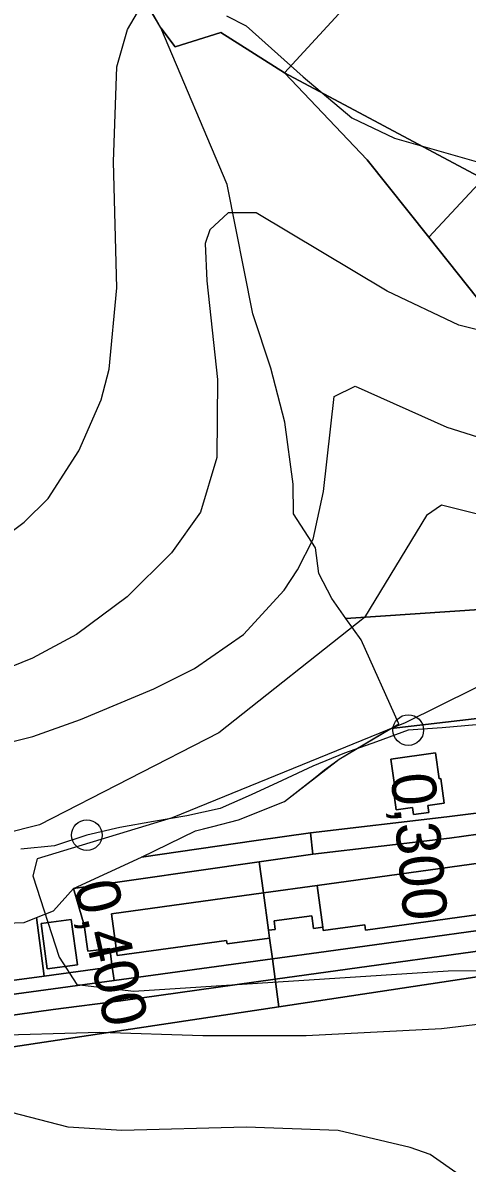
# Model space of a CAD drawing. Extents: x -510989 to -501240, y -1184665 to -1176089.
# Drawn here: x -504976.6 to -504845.9, y -1180942.6 to -1180607.1 of the extents above; entities that cross this region are included whole.
import ezdxf

# ---------------------------------------------------------------- set-up
doc = ezdxf.new("R2010")
doc.units = 0
for name, color, linetype in [('lesni_pozemek', 7, 'Continuous'), ('ostatni_plocha_x_draha', 7, 'Continuous'), ('ostatni_plocha_x_manipulacni_plocha', 7, 'Continuous'), ('popis', 7, 'Continuous'), ('STAV_zaplavove_uzemi', 7, 'Continuous'), ('trasovani_toku', 7, 'Continuous'), ('trvaly_travni_porost', 7, 'Continuous'), ('vrstevnice_01', 7, 'Continuous'), ('vrstevnice_02', 7, 'Continuous'), ('zastavena_plocha_a_nadvori', 7, 'Continuous')]:
    doc.layers.add(name, color=color, linetype=linetype)

msp = doc.modelspace()

# ---------------------------------------------------------------- linework, layer by layer
at = {"layer": 'lesni_pozemek'}
for points in [[(-504778.12, -1180775.36), (-504881.56, -1180782.32), (-504885.75, -1180776.42), (-504889.55, -1180769.13), (-504890.55, -1180761.5), (-504896.97, -1180751.57), (-504897.07, -1180742.79), (-504899.58, -1180724.53), (-504903.69, -1180708.68), (-504909, -1180692.68), (-504916.51, -1180654.59), (-504935.99, -1180608.54), (-504931.77, -1180614.16), (-504918.37, -1180609.9), (-504899.64, -1180621.82), (-504875.35, -1180647.35), (-504857.2, -1180670.16), (-504840.1, -1180691.66)], [(-505061.03, -1180977.99), (-505070, -1180922), (-504901.28, -1180896.57), (-504813.81, -1180883.39), (-504775.02, -1180922.63), (-504752.9, -1180947.58)]]:
    msp.add_lwpolyline(points, dxfattribs=at)
msp.add_lwpolyline([(-504778.12, -1180775.36), (-504774.09, -1180803.74), (-504868.25, -1180814.65), (-504865.99, -1180813.32), (-504877.12, -1180788.56), (-504881.56, -1180782.32)], close=True, dxfattribs=at)
at = {"layer": 'ostatni_plocha_x_draha'}
for points in [[(-504813.52, -1180870.15), (-504809.78, -1180869.64), (-504808.97, -1180875.47), (-504820.1, -1180877.02), (-504902.38, -1180888.46), (-504903.2, -1180882.42), (-504887.4, -1180880.26)], [(-504903.2, -1180882.42), (-504902.38, -1180888.46), (-504947.79, -1180894.78), (-504967.64, -1180897.41), (-505034.97, -1180906.78), (-505082.62, -1180915.45), (-505097.23, -1180920.86), (-505099.02, -1180907.99), (-505090.37, -1180907.46), (-505082.68, -1180906.98), (-504949.75, -1180888.79)]]:
    msp.add_lwpolyline(points, close=True, dxfattribs=at)
at = {"layer": 'ostatni_plocha_x_manipulacni_plocha'}
for points in [[(-504794.68, -1180513.8), (-504787.11, -1180516.78), (-504752.69, -1180548.72), (-504748.1, -1180552.99), (-504841.23, -1180653), (-504899.64, -1180621.82), (-504883.7, -1180604.44), (-504828.67, -1180545.06), (-504805.78, -1180520.45), (-504801.13, -1180516)], [(-504729.03, -1180772.34), (-504722.98, -1180823.87), (-504772.69, -1180830.81), (-504851.89, -1180840.66), (-504891.96, -1180845.4), (-504907.99, -1180847.69), (-504941.74, -1180852.51), (-504925.8, -1180844.85), (-504920.73, -1180843.54), (-504913.22, -1180841.6), (-504899.67, -1180836.13), (-504890.59, -1180829.07), (-504887.89, -1180826.89), (-504883.58, -1180823.67), (-504871.07, -1180816.31), (-504868.25, -1180814.65), (-504774.09, -1180803.74), (-504778.12, -1180775.36)], [(-504868.37, -1180823.7), (-504867.33, -1180831.28), (-504867.82, -1180831.35), (-504866.82, -1180838.63), (-504861.96, -1180837.96), (-504861.69, -1180839.99), (-504857.23, -1180839.38), (-504857.51, -1180837.35), (-504852.65, -1180836.69), (-504853.65, -1180829.4), (-504854.15, -1180829.46), (-504855.19, -1180821.88)], [(-504907.99, -1180847.69), (-504891.96, -1180845.4), (-504891.28, -1180851.67), (-504907.12, -1180853.94), (-504961.67, -1180861.76), (-504941.74, -1180852.51)], [(-504907.12, -1180853.94), (-504905.86, -1180863.03), (-504950.53, -1180869.21), (-504948.83, -1180881.52), (-504916.66, -1180877.04), (-504916.52, -1180878.08), (-504904.04, -1180876.34), (-504903.2, -1180882.42), (-504949.75, -1180888.79), (-504950.31, -1180884.77), (-504951.06, -1180879.42), (-504957.51, -1180880.25), (-504958.55, -1180872.52), (-504961.67, -1180861.76)], [(-504967.56, -1180868.31), (-504961.67, -1180861.76), (-504958.55, -1180872.52), (-504957.51, -1180880.25), (-504951.06, -1180879.42), (-504950.31, -1180884.77), (-504970.29, -1180887.57), (-504972.62, -1180870.33)], [(-504976.25, -1180871.79), (-504972.62, -1180870.33), (-504970.29, -1180887.57), (-505005.53, -1180892.29), (-505008.04, -1180869.77), (-504995.29, -1180872.45)], [(-504962.35, -1180870.89), (-504971.22, -1180872.11), (-504969.42, -1180885.39), (-504960.55, -1180884.19)], [(-504820.1, -1180877.02), (-504808.97, -1180875.47), (-504808, -1180882.51), (-504813.81, -1180883.39), (-504901.28, -1180896.57), (-504902.38, -1180888.46)]]:
    msp.add_lwpolyline(points, close=True, dxfattribs=at)
for points in [[(-504883.7, -1180604.44), (-504899.64, -1180621.82), (-504918.37, -1180609.9), (-504931.77, -1180614.16), (-504935.99, -1180608.54), (-504945.65, -1180591.49)], [(-504586.22, -1180827.45), (-504620.9, -1180827.94), (-504638.76, -1180828.03), (-504676.14, -1180828.22), (-504700.58, -1180828.72), (-504724.11, -1180830.13), (-504767.04, -1180835.38), (-504813.61, -1180841.75), (-504817.37, -1180842.26), (-504851.11, -1180846.92), (-504891.28, -1180851.67), (-504891.96, -1180845.4), (-504851.89, -1180840.66), (-504772.69, -1180830.81), (-504722.98, -1180823.87), (-504702, -1180822.23), (-504678.51, -1180822.08), (-504634.51, -1180821.81), (-504620.72, -1180821.72), (-504586.77, -1180821.19)], [(-504824.09, -1180851.79), (-504890.06, -1180860.84), (-504905.86, -1180863.03), (-504907.12, -1180853.94), (-504891.28, -1180851.67), (-504851.11, -1180846.92), (-504817.37, -1180842.26)], [(-504813.52, -1180870.15), (-504887.4, -1180880.26), (-504903.2, -1180882.42), (-504904.04, -1180876.34), (-504904.35, -1180874.06), (-504902.37, -1180873.79), (-504902.71, -1180871.31), (-504891.61, -1180869.79), (-504891.09, -1180873.55), (-504888.37, -1180873.18), (-504888.23, -1180874.17), (-504876, -1180872.49), (-504875.79, -1180873.98), (-504827.55, -1180867.35)], [(-505005.53, -1180892.29), (-504970.29, -1180887.57), (-504950.31, -1180884.77), (-504949.75, -1180888.79), (-505082.68, -1180906.98)], [(-505034.97, -1180906.78), (-504967.64, -1180897.41), (-504947.79, -1180894.78), (-504902.38, -1180888.46), (-504901.28, -1180896.57), (-505070, -1180922)]]:
    msp.add_lwpolyline(points, dxfattribs=at)
at = {"layer": 'popis'}
msp.add_lwpolyline([(-504995.29, -1180872.45), (-504976.25, -1180871.79), (-504972.62, -1180870.33), (-504967.56, -1180868.31), (-504961.67, -1180861.76), (-504941.74, -1180852.51), (-504925.8, -1180844.85), (-504913.22, -1180841.6), (-504899.67, -1180836.13), (-504883.58, -1180823.67), (-504865.99, -1180813.32), (-504877.12, -1180788.56), (-504881.56, -1180782.32), (-504885.75, -1180776.42), (-504889.55, -1180769.13), (-504890.55, -1180761.5), (-504896.97, -1180751.57), (-504897.07, -1180742.79), (-504899.58, -1180724.53), (-504903.69, -1180708.68), (-504909, -1180692.68), (-504916.51, -1180654.59), (-504935.99, -1180608.54), (-504968.37, -1180553.81)], dxfattribs=at)
at = {"layer": 'STAV_zaplavove_uzemi'}
msp.add_spline([(-504826.46, -1182247.73), (-504827.62, -1182204.68), (-504817.15, -1182165.12), (-504791.55, -1182113.93), (-504727.56, -1182034.81), (-504708.94, -1182017.35), (-504669.38, -1181991.76), (-504649.6, -1181961.5), (-504628.66, -1181917.29), (-504601.9, -1181867.26), (-504597.24, -1181809.08), (-504585.16, -1181766.79), (-504596.8, -1181741.4), (-504604.2, -1181726.59), (-504633.82, -1181658.9), (-504646.51, -1181600.72), (-504660.26, -1181556.29), (-504751.04, -1181459.08), (-504798.4, -1181384.84), (-504826.55, -1181347.73), (-504862.39, -1181315.73), (-504866.23, -1181265.81), (-504862.39, -1181205.66), (-504853.43, -1181164.7), (-504793.92, -1181116.47), (-504755.84, -1181064.64), (-504725.17, -1181018.1), (-504649.01, -1180947.23), (-504594, -1180900.69), (-504545.35, -1180879.53), (-504377.38, -1180832.83), (-504317.01, -1180808.36), (-504368.93, -1180802.59), (-504426.63, -1180826.63), (-504542.02, -1180859.32)], degree=3, dxfattribs=at)
at = {"layer": 'trasovani_toku'}
for p, q in [((-504863.23, -1180815.15), (-504872.6, -1180818.66)), ((-504853.26, -1180814.46), (-504863.23, -1180815.15)), ((-504843.29, -1180813.6), (-504853.26, -1180814.46)), ((-504872.6, -1180818.66), (-504882.04, -1180821.94)), ((-504882.04, -1180821.94), (-504891.27, -1180825.8)), ((-504891.27, -1180825.8), (-504900.35, -1180829.99)), ((-504900.35, -1180829.99), (-504909.42, -1180834.19)), ((-504909.42, -1180834.19), (-504918.56, -1180838.26)), ((-504918.56, -1180838.26), (-504928.34, -1180840.35)), ((-504938.19, -1180842.06), (-504948.03, -1180843.83)), ((-504928.34, -1180840.35), (-504938.19, -1180842.06)), ((-504957.78, -1180846.07), (-504967.28, -1180849.19)), ((-504948.03, -1180843.83), (-504957.78, -1180846.07)), ((-504967.28, -1180849.19), (-504977.23, -1180850.18))]:
    msp.add_line(p, q, dxfattribs=at)
for centre in [(-504863.23, -1180815.15), (-504957.78, -1180846.07)]:
    msp.add_circle(centre, 4.5, dxfattribs=at)
at = {"layer": 'trvaly_travni_porost'}
for points in [[(-504875.35, -1180647.35), (-504899.64, -1180621.82), (-504841.23, -1180653), (-504857.2, -1180670.16)], [(-504841.23, -1180653), (-504745.8, -1180703.95), (-504702.57, -1180727.02), (-504697, -1180730), (-504696.34, -1180738.75), (-504714.5, -1180740.39), (-504732.28, -1180732.9), (-504736.03, -1180735.08), (-504781.24, -1180713.72), (-504801.06, -1180715.91), (-504840.1, -1180691.66), (-504857.2, -1180670.16)]]:
    msp.add_lwpolyline(points, close=True, dxfattribs=at)
at = {"layer": 'vrstevnice_01'}
for points in [[(-504828.31, -1180701), (-504848.41, -1180696), (-504869.41, -1180686), (-504908, -1180663), (-504916.19, -1180663), (-504921.59, -1180668), (-504923, -1180672), (-504922.5, -1180683), (-504919.31, -1180712), (-504919.59, -1180735), (-504924.31, -1180751), (-504932.91, -1180763), (-504945.91, -1180776), (-504960.81, -1180787), (-504973.81, -1180794), (-504988.59, -1180800)], [(-504611.91, -1180776), (-504652.81, -1180783), (-504695.91, -1180784), (-504731.19, -1180783), (-504746.31, -1180779), (-504783.09, -1180763), (-504798.81, -1180759), (-504829.41, -1180755), (-504853.5, -1180749), (-504857.91, -1180752), (-504876.09, -1180782), (-504918.91, -1180816), (-504971.69, -1180843), (-505023.09, -1180856)], [(-505022.5, -1180906), (-504953.91, -1180904), (-504923.69, -1180905), (-504893.31, -1180905), (-504853.5, -1180903), (-504811.81, -1180898), (-504799.5, -1180902), (-504780.19, -1180913), (-504770.41, -1180923), (-504766.59, -1180931), (-504765.59, -1180946)]]:
    msp.add_lwpolyline(points, dxfattribs=at)
at = {"layer": 'vrstevnice_02'}
for points in [[(-504916.69, -1180605), (-504910.91, -1180608), (-504894.19, -1180623), (-504879.81, -1180635), (-504867.31, -1180641), (-504825.41, -1180653), (-504803.81, -1180655), (-504781.91, -1180655), (-504770.5, -1180651), (-504764.09, -1180649), (-504758.41, -1180645), (-504751.31, -1180638), (-504747, -1180632), (-504735.81, -1180609), (-504733.91, -1180601)], [(-505046.91, -1180779), (-505034.31, -1180778), (-505025.09, -1180776), (-505008.81, -1180772), (-504988.31, -1180763), (-504976.19, -1180754), (-504969.19, -1180747), (-504960.09, -1180733), (-504953.59, -1180718), (-504951.19, -1180709), (-504948.91, -1180685), (-504949.91, -1180648), (-504948.91, -1180620), (-504945.81, -1180609), (-504942.91, -1180604)], [(-504888.19, -1180745), (-504885, -1180717), (-504878.81, -1180714), (-504851.91, -1180726), (-504826.69, -1180734), (-504792.19, -1180739), (-504765.5, -1180746), (-504743.69, -1180751), (-504711.41, -1180753), (-504690, -1180752), (-504650, -1180748), (-504633.19, -1180744), (-504600.81, -1180739)], [(-505179.5, -1180837), (-505149.31, -1180831), (-505130.41, -1180831), (-505075.81, -1180833), (-505039, -1180830), (-505001.81, -1180824), (-504973.69, -1180817), (-504959.69, -1180812), (-504938.09, -1180803), (-504926.09, -1180797), (-504911.69, -1180787), (-504899.69, -1180774), (-504895.81, -1180768), (-504891.19, -1180759), (-504888.19, -1180745)], [(-504833.81, -1180798), (-504864.19, -1180813), (-504932.69, -1180841), (-504972.41, -1180853), (-504973.69, -1180858), (-504965.91, -1180882), (-504960.69, -1180890), (-504943.91, -1180892), (-504851.5, -1180886), (-504767.41, -1180885)], [(-504848.31, -1180946), (-504856.81, -1180940), (-504862.69, -1180938), (-504883.81, -1180933), (-504910.91, -1180932), (-504947.5, -1180933), (-504963.31, -1180932), (-504994.09, -1180924), (-505006.19, -1180923), (-505022.19, -1180923), (-505044.5, -1180928), (-505050.91, -1180931), (-505056.59, -1180935), (-505061.91, -1180941), (-505067.09, -1180949)]]:
    msp.add_lwpolyline(points, dxfattribs=at)
at = {"layer": 'zastavena_plocha_a_nadvori'}
for points in [[(-504868.37, -1180823.7), (-504855.19, -1180821.88), (-504854.15, -1180829.46), (-504853.65, -1180829.4), (-504852.65, -1180836.69), (-504857.51, -1180837.35), (-504857.23, -1180839.38), (-504861.69, -1180839.99), (-504861.96, -1180837.96), (-504866.82, -1180838.63), (-504867.82, -1180831.35), (-504867.33, -1180831.28)], [(-504824.09, -1180851.79), (-504822.26, -1180865.11), (-504827.76, -1180865.86), (-504827.55, -1180867.35), (-504875.79, -1180873.98), (-504876, -1180872.49), (-504888.23, -1180874.17), (-504888.37, -1180873.18), (-504890.06, -1180860.84)], [(-504905.86, -1180863.03), (-504904.35, -1180874.06), (-504904.04, -1180876.34), (-504916.52, -1180878.08), (-504916.66, -1180877.04), (-504948.83, -1180881.52), (-504950.53, -1180869.21)], [(-504905.86, -1180863.03), (-504890.06, -1180860.84), (-504888.37, -1180873.18), (-504891.09, -1180873.55), (-504891.61, -1180869.79), (-504902.71, -1180871.31), (-504902.37, -1180873.79), (-504904.35, -1180874.06)], [(-504962.35, -1180870.89), (-504960.55, -1180884.19), (-504969.42, -1180885.39), (-504971.22, -1180872.11)]]:
    msp.add_lwpolyline(points, close=True, dxfattribs=at)

# ---------------------------------------------------------------- texts
at = {"layer": 'trasovani_toku'}
for s, rotation, p in [('0,300', 275.0846, (-504868.37, -1180828.28)), ('0,400', 282.5819, (-504961.71, -1180860.79))]:
    msp.add_text(s, height=13, rotation=rotation, dxfattribs=at).set_placement(p)

doc.saveas('drawing.dxf')
